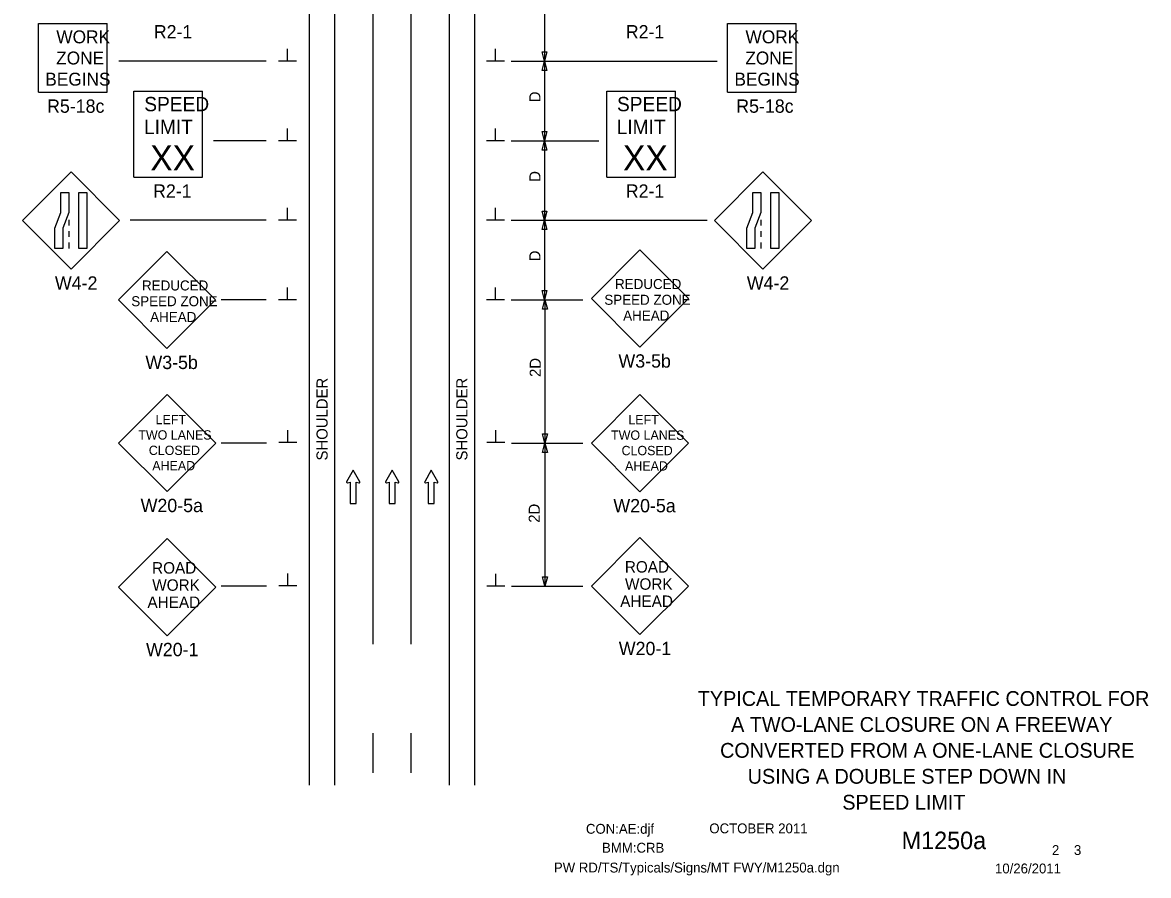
# Model space of a CAD drawing. Extents: x 16576 to 19508, y 5728 to 6974.
# Drawn here: x 17765 to 18473, y 5932 to 6468 of the extents above; entities that cross this region are included whole.
import ezdxf

# ---------------------------------------------------------------- set-up
doc = ezdxf.new("R2010")
doc.units = 0
for name, color, linetype in [('ALI_LEGAL_EX', 7, 'Continuous'), ('BORDER', 7, 'Continuous'), ('BORDER_SIGNAL_WO', 7, 'Continuous'), ('MT_SCRATCH_LEVEL_E', 7, 'Continuous'), ('PAVT_EDGE_EX', 7, 'Continuous'), ('TRAFFIC_SIGNS_PR', 7, 'Continuous'), ('TYPICAL_TEXT_DIMEN_PR', 7, 'Continuous')]:
    doc.layers.add(name, color=color, linetype=linetype)

msp = doc.modelspace()

# ---------------------------------------------------------------- linework, layer by layer
at = {"layer": 'ALI_LEGAL_EX'}
for p, q in [((17985.63, 6921.33), (17985.63, 6077.19)), ((18009.63, 6921.33), (18009.63, 6077.19))]:
    msp.add_line(p, q, dxfattribs=at)
for points in [[(17985.63, 6421.33), (17985.63, 6396.33)], [(18009.63, 6421.33), (18009.63, 6396.33)], [(17985.63, 6321.33), (17985.63, 6296.33)], [(18009.63, 6321.33), (18009.63, 6296.33)], [(17985.63, 6221.33), (17985.63, 6196.33)], [(18009.63, 6221.33), (18009.63, 6196.33)], [(17985.63, 6121.33), (17985.63, 6096.33)], [(18009.63, 6121.33), (18009.63, 6096.33)], [(17985.63, 6021.33), (17985.63, 5996.33)], [(18009.63, 6021.33), (18009.63, 5996.33)]]:
    msp.add_lwpolyline(points, dxfattribs=at)
at = {"layer": 'MT_SCRATCH_LEVEL_E'}
for p, q in [((17973.31, 6186.57), (17969.2, 6179.33)), ((17977.46, 6179.33), (17973.31, 6186.57)), ((17997.84, 6186.57), (17993.73, 6179.33)), ((18001.99, 6179.33), (17997.84, 6186.57)), ((18022.4, 6186.57), (18018.29, 6179.33)), ((18026.55, 6179.33), (18022.4, 6186.57)), ((17969.68, 6178.65), (17971.46, 6178.96)), ((17971.46, 6178.96), (17971.46, 6165.71)), ((17975.2, 6165.71), (17975.2, 6178.96)), ((17975.2, 6178.96), (17976.98, 6178.65)), ((17994.21, 6178.65), (17995.99, 6178.96)), ((17995.99, 6178.96), (17995.99, 6165.71)), ((17999.73, 6165.71), (17999.73, 6178.96)), ((17999.73, 6178.96), (18001.51, 6178.65)), ((18018.77, 6178.65), (18020.55, 6178.96)), ((18020.55, 6178.96), (18020.55, 6165.71)), ((18024.29, 6165.71), (18024.29, 6178.96)), ((18024.29, 6178.96), (18026.07, 6178.65)), ((17971.46, 6165.71), (17975.2, 6165.71)), ((17995.99, 6165.71), (17999.73, 6165.71)), ((18020.55, 6165.71), (18024.29, 6165.71))]:
    msp.add_line(p, q, dxfattribs=at)
for centre, start, end in [((17969.61, 6179.11), 150.42484, 279.96381), ((17977.05, 6179.11), 260.03619, 29.77312), ((17994.14, 6179.11), 150.42484, 279.96381), ((18001.58, 6179.11), 260.03619, 29.77312), ((18018.7, 6179.11), 150.42484, 279.96381), ((18026.14, 6179.11), 260.03619, 29.77312)]:
    msp.add_arc(centre, 0.463, start, end, dxfattribs=at)
at = {"layer": 'PAVT_EDGE_EX'}
for p, q in [((17945.63, 6921.33), (17945.63, 5988.51)), ((17961.63, 6921.33), (17961.63, 5988.51)), ((18033.63, 6921.33), (18033.63, 5988.51)), ((18049.63, 6921.33), (18049.63, 5988.51))]:
    msp.add_line(p, q, dxfattribs=at)
at = {"layer": 'TRAFFIC_SIGNS_PR'}
for p, q in [((17775.4, 6424.1), (17775.4, 6467.3)), ((17775.4, 6467.3), (17818.6, 6467.3)), ((17818.6, 6424.1), (17818.6, 6467.3)), ((18208.79, 6424.1), (18208.79, 6467.3)), ((18208.79, 6467.3), (18251.99, 6467.3)), ((18251.99, 6424.1), (18251.99, 6467.3)), ((17775.4, 6424.1), (17818.6, 6424.1)), ((17835.46, 6424.73), (17878.66, 6424.73)), ((17835.46, 6370.73), (17835.46, 6424.73)), ((17878.66, 6370.73), (17878.66, 6424.73)), ((18132.73, 6424.73), (18175.93, 6424.73)), ((18132.73, 6370.73), (18132.73, 6424.73)), ((18175.93, 6370.73), (18175.93, 6424.73)), ((18208.79, 6424.1), (18251.99, 6424.1)), ((17795.93, 6374.01), (17765.38, 6343.46)), ((17826.47, 6343.46), (17795.93, 6374.01)), ((18231.02, 6374.01), (18200.48, 6343.46)), ((18261.57, 6343.46), (18231.02, 6374.01)), ((17835.46, 6370.73), (17878.66, 6370.73)), ((18132.73, 6370.73), (18175.93, 6370.73)), ((17765.38, 6343.46), (17795.93, 6312.92)), ((17794.52, 6344.02), (17794.52, 6340.42)), ((17795.93, 6312.92), (17826.47, 6343.46)), ((18200.48, 6343.46), (18231.02, 6312.92)), ((18229.62, 6344.02), (18229.62, 6340.42)), ((18231.02, 6312.92), (18261.57, 6343.46)), ((17794.52, 6336.82), (17794.52, 6333.22)), ((18229.62, 6336.82), (18229.62, 6333.22)), ((17794.52, 6329.62), (17794.52, 6326.02)), ((17856.22, 6324.11), (17825.67, 6293.57)), ((17886.77, 6293.57), (17856.22, 6324.11)), ((18153.68, 6325.01), (18123.14, 6294.47)), ((18184.23, 6294.47), (18153.68, 6325.01)), ((18229.62, 6329.62), (18229.62, 6326.02)), ((17825.67, 6293.57), (17856.22, 6263.02)), ((17856.22, 6263.02), (17886.77, 6293.57)), ((18123.14, 6294.47), (18153.68, 6263.92)), ((18153.68, 6263.92), (18184.23, 6294.47)), ((17856.37, 6234.19), (17825.82, 6203.64)), ((17886.91, 6203.64), (17856.37, 6234.19)), ((18153.67, 6234.05), (18123.12, 6203.5)), ((18184.21, 6203.5), (18153.67, 6234.05)), ((17825.82, 6203.64), (17856.37, 6173.09)), ((17856.37, 6173.09), (17886.91, 6203.64)), ((18123.12, 6203.5), (18153.67, 6172.95)), ((18153.67, 6172.95), (18184.21, 6203.5)), ((17856.36, 6143.64), (17825.81, 6113.09)), ((17886.9, 6113.09), (17856.36, 6143.64)), ((18153.65, 6144.29), (18123.11, 6113.75)), ((18184.2, 6113.75), (18153.65, 6144.29)), ((17825.81, 6113.09), (17856.36, 6082.55)), ((17856.36, 6082.55), (17886.9, 6113.09)), ((18123.11, 6113.75), (18153.65, 6083.2)), ((18153.65, 6083.2), (18184.2, 6113.75))]:
    msp.add_line(p, q, dxfattribs=at)
for points in [[(17794.52, 6361.17), (17794.52, 6348.59), (17790.76, 6338.6), (17790.76, 6326.02), (17785.71, 6326.02), (17785.71, 6338.6), (17789.47, 6348.59), (17789.47, 6361.17)], [(17805.93, 6361.17), (17805.93, 6326.02), (17800.87, 6326.02), (17800.87, 6361.17)], [(18229.62, 6361.17), (18229.62, 6348.59), (18225.86, 6338.6), (18225.86, 6326.02), (18220.8, 6326.02), (18220.8, 6338.6), (18224.56, 6348.59), (18224.56, 6361.17)], [(18241.02, 6361.17), (18241.02, 6326.02), (18235.97, 6326.02), (18235.97, 6361.17)]]:
    msp.add_lwpolyline(points, close=True, dxfattribs=at)
at = {"layer": 'TYPICAL_TEXT_DIMEN_PR'}
for p, q in [((18093.63, 6493.63), (18093.63, 6443.63)), ((17932.02, 6443.63), (17932.02, 6451.41)), ((18062.76, 6443.63), (18062.76, 6451.41)), ((17918.58, 6443.63), (17825.89, 6443.63)), ((17937.64, 6443.63), (17926.39, 6443.63)), ((18068.38, 6443.63), (18057.13, 6443.63)), ((18072.63, 6443.63), (18202.12, 6443.63)), ((18093.63, 6443.63), (18092.06, 6449.49)), ((18092.06, 6449.49), (18093.63, 6449.49)), ((18092.06, 6437.77), (18093.63, 6443.63)), ((18093.63, 6449.49), (18095.2, 6449.49)), ((18095.2, 6449.49), (18093.63, 6443.63)), ((18093.63, 6443.63), (18095.2, 6437.77)), ((18093.63, 6443.63), (18093.63, 6393.63)), ((18093.63, 6437.77), (18092.06, 6437.77)), ((18095.2, 6437.77), (18093.63, 6437.77)), ((17932.02, 6393.63), (17932.02, 6401.41)), ((18062.76, 6393.63), (18062.76, 6401.41)), ((18093.63, 6393.63), (18092.06, 6399.49)), ((18092.06, 6399.49), (18093.63, 6399.49)), ((18093.63, 6399.49), (18095.2, 6399.49)), ((18095.2, 6399.49), (18093.63, 6393.63)), ((17918.58, 6393.63), (17885.49, 6393.63)), ((17937.64, 6393.63), (17926.39, 6393.63)), ((18068.38, 6393.63), (18057.13, 6393.63)), ((18072.63, 6393.63), (18127.76, 6393.63)), ((18092.06, 6387.77), (18093.63, 6393.63)), ((18093.63, 6387.77), (18092.06, 6387.77)), ((18093.63, 6393.63), (18093.63, 6343.63)), ((18093.63, 6393.63), (18095.2, 6387.77)), ((18095.2, 6387.77), (18093.63, 6387.77)), ((17932.02, 6343.63), (17932.02, 6351.41)), ((18062.76, 6343.63), (18062.76, 6351.41)), ((18093.63, 6343.63), (18092.06, 6349.49)), ((18092.06, 6349.49), (18093.63, 6349.49)), ((18093.63, 6349.49), (18095.2, 6349.49)), ((18095.2, 6349.49), (18093.63, 6343.63)), ((17918.58, 6343.63), (17833.07, 6343.63)), ((17937.64, 6343.63), (17926.39, 6343.63)), ((18068.38, 6343.63), (18057.13, 6343.63)), ((18072.63, 6343.63), (18195.84, 6343.63)), ((18092.06, 6337.77), (18093.63, 6343.63)), ((18093.63, 6337.77), (18092.06, 6337.77)), ((18093.63, 6343.63), (18093.63, 6293.63)), ((18093.63, 6343.63), (18095.2, 6337.77)), ((18095.2, 6337.77), (18093.63, 6337.77)), ((17932.02, 6293.63), (17932.02, 6301.41)), ((18062.76, 6293.63), (18062.76, 6301.41)), ((18093.63, 6293.63), (18092.06, 6299.49)), ((18092.06, 6299.49), (18093.63, 6299.49)), ((18093.63, 6299.49), (18095.2, 6299.49)), ((18095.2, 6299.49), (18093.63, 6293.63)), ((17918.58, 6293.63), (17890.39, 6293.63)), ((17937.64, 6293.63), (17926.39, 6293.63)), ((18068.38, 6293.63), (18057.13, 6293.63)), ((18072.63, 6293.63), (18117.77, 6293.63)), ((18092.3, 6287.77), (18093.87, 6293.63)), ((18093.87, 6287.77), (18092.3, 6287.77)), ((18093.87, 6293.63), (18093.87, 6203.63)), ((18093.87, 6293.63), (18095.44, 6287.77)), ((18095.44, 6287.77), (18093.87, 6287.77)), ((17932.26, 6203.95), (17932.26, 6211.74)), ((18063, 6203.95), (18063, 6211.74)), ((17918.81, 6203.63), (17890.39, 6203.63)), ((17937.88, 6203.95), (17926.63, 6203.95)), ((18068.62, 6203.95), (18057.37, 6203.95)), ((18072.87, 6203.63), (18117.77, 6203.63)), ((18093.87, 6203.63), (18092.3, 6209.49)), ((18092.3, 6209.49), (18093.87, 6209.49)), ((18092.3, 6197.77), (18093.87, 6203.63)), ((18093.87, 6209.49), (18095.44, 6209.49)), ((18095.44, 6209.49), (18093.87, 6203.63)), ((18093.87, 6203.63), (18093.87, 6113.63)), ((18093.87, 6203.63), (18095.44, 6197.77)), ((18093.87, 6197.77), (18092.3, 6197.77)), ((18095.44, 6197.77), (18093.87, 6197.77)), ((17932.26, 6113.9), (17932.26, 6121.68)), ((18063, 6113.63), (18063, 6121.41)), ((18093.87, 6113.63), (18092.3, 6119.49)), ((18092.3, 6119.49), (18093.87, 6119.49)), ((18093.87, 6119.49), (18095.44, 6119.49)), ((18095.44, 6119.49), (18093.87, 6113.63)), ((17918.81, 6113.63), (17890.39, 6113.63)), ((17937.88, 6113.9), (17926.63, 6113.9)), ((18068.62, 6113.63), (18057.37, 6113.63)), ((18072.87, 6113.63), (18117.77, 6113.63))]:
    msp.add_line(p, q, dxfattribs=at)

# ---------------------------------------------------------------- texts
at = {"layer": 'BORDER'}
for s, p in [('TYPICAL TEMPORARY TRAFFIC CONTROL FOR', (18190.04, 6038.42)), ('A TWO-LANE CLOSURE ON A FREEWAY', (18210.99, 6022.12)), ('CONVERTED FROM A ONE-LANE CLOSURE', (18204.06, 6005.82)), ('USING A DOUBLE STEP DOWN IN ', (18221.42, 5989.52)), ('SPEED LIMIT', (18280.92, 5973.22))]:
    msp.add_text(s, height=9.3, dxfattribs=at).set_placement(p)
at = {"layer": 'BORDER_SIGNAL_WO'}
for s, height, p in [('CON:AE:djf  ', 6.2, (18119.69, 5958.06)), ('    OCTOBER 2011    ', 6.2, (18188.08, 5958.34)), ('    M1250a   ', 11, (18301.86, 5948.38)), ('BMM:CRB   ', 6.2, (18129.81, 5946.17)), (' 2    3 ', 6.2, (18410.45, 5944.7)), ('PW RD/TS/Typicals/Signs/MT FWY/M1250a.dgn      ', 6.2, (18099.55, 5933.71)), ('10/26/2011    ', 6.2, (18376.93, 5933.13))]:
    msp.add_text(s, height=height, dxfattribs=at).set_placement(p)
at = {"layer": 'TRAFFIC_SIGNS_PR'}
for s, height, p in [('R2-1', 8.37, (17847.92, 6457.97)), ('R2-1', 8.37, (18144.74, 6457.97)), ('WORK', 8.119, (17786.65, 6454.88)), ('WORK', 8.119, (18220.04, 6454.88)), ('ZONE', 8.119, (17786.52, 6441.6)), ('ZONE', 8.119, (18219.91, 6441.6)), ('BEGINS', 8.119, (17779.69, 6428.31)), ('BEGINS', 8.119, (18213.08, 6428.31)), ('R5-18c', 8.37, (17780.81, 6411.23)), ('SPEED', 9, (17841.95, 6412.2)), ('SPEED', 9, (18139.22, 6412.2)), ('R5-18c', 8.37, (18214.2, 6411.23)), ('LIMIT', 9, (17841.77, 6397.8)), ('LIMIT', 9, (18139.04, 6397.8)), ('XX', 15.785, (17845.71, 6374.95)), ('XX', 15.785, (18142.98, 6374.95)), ('R2-1', 8.37, (17847.47, 6357.86)), ('R2-1', 8.37, (18144.74, 6357.86)), ('W4-2', 8.37, (17785.76, 6300.05)), ('REDUCED', 6.3, (17840.53, 6299.54)), ('REDUCED', 6.3, (18138, 6300.44)), ('W4-2', 8.37, (18220.85, 6300.05)), ('SPEED ZONE', 6.3, (17833.77, 6289.64)), ('SPEED ZONE', 6.3, (18131.24, 6290.54)), ('AHEAD', 6.3, (17845.65, 6279.74)), ('AHEAD', 6.3, (18143.12, 6280.64)), ('W3-5b', 8.37, (18140.13, 6251.05)), ('W3-5b', 8.37, (17842.67, 6250.15)), ('LEFT', 5.85, (17849.1, 6215.49)), ('LEFT', 5.85, (18146.39, 6215.35)), ('TWO LANES', 5.85, (17838.21, 6205.82)), ('TWO LANES', 5.85, (18135.51, 6205.68)), ('CLOSED', 5.85, (17844.8, 6196.14)), ('CLOSED', 5.85, (18142.09, 6196)), ('AHEAD', 5.85, (17846.99, 6186.47)), ('AHEAD', 5.85, (18144.28, 6186.33)), ('W20-5a', 8.37, (17839.65, 6160.22)), ('W20-5a', 8.37, (18136.95, 6160.09)), ('ROAD', 7.2, (17846.84, 6121.57)), ('ROAD', 7.2, (18144.14, 6122.22)), ('WORK', 7.2, (17846.96, 6110.77)), ('WORK', 7.2, (18144.26, 6111.42)), ('AHEAD', 7.2, (17843.94, 6099.97)), ('AHEAD', 7.2, (18141.24, 6100.62)), ('W20-1', 8.37, (17843.05, 6069.68)), ('W20-1', 8.37, (18140.35, 6070.33))]:
    msp.add_text(s, height=height, dxfattribs=at).set_placement(p)
at = {"layer": 'TYPICAL_TEXT_DIMEN_PR'}
for s, p in [('D', (18091.08, 6417.85)), ('D', (18091.08, 6367.85)), ('D', (18091.08, 6317.85)), ('2D', (18091.31, 6245.15)), ('SHOULDER', (17957.25, 6192.68)), ('SHOULDER', (18045.15, 6192.68)), ('2D', (18090.67, 6153.54))]:
    msp.add_text(s, height=7, rotation=90, dxfattribs=at).set_placement(p)

doc.saveas('drawing.dxf')
